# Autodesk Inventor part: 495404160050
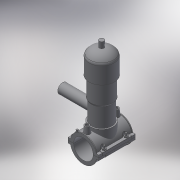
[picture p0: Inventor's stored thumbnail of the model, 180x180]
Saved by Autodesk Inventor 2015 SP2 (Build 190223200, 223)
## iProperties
Created: 2017-07
Part Number: 495404160050
Material: Generic
Description: PLASSON TAPPING VALVE 160-50
Document SubType Name: Modeling
Designer: KIM
Density: 1 g/cm^3
Appearance: Default
Author: KIM
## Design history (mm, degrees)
derived "495404-4954S4.ipt"
feature "Solid1::495404-4954S4.ipt"
feature "Solid2::495404-4954S4.ipt"
tag "TaggingFeature1"
body "Solid1"
body "Solid2"
other parameters: "d2" = 202, "d4" = 118, "d5" = 0, "d6" = 0.1, "d8" = 0, "d19" = 6, "d20" = 6, "d21" = 70.8, "d23" = 0, "d24" = 35.4, "d26" = 0, "d27" = 3, "d28" = 3, "d29" = 3, "d30" = 53.33333, "d31" = 6, "d32" = 0, "d33" = 0, "d34" = 0.6, "d40" = 99.84, "d47" = 147, "d70" = 15, "d72" = 0, "d73" = 6, "d75" = 5, "d76" = 0, "d77" = 8, "d79" = 15, "d80" = 47.2, "d82" = 5 deg, "d84" = 4, "d85" = 14, "d86" = 0, "d87" = 3, "d88" = 0, "d89" = 1, "d90" = 1, "d91" = 94.4, "d92" = 0, "d93" = 0.5, "d94" = 84.21053, "d96" = 197.76, "d97" = 2.36, "d98" = 0, "d120" = 140 deg, "d121" = 24.228, "d122" = 20 deg, "d123" = 384, "d124" = 115.2, "d126" = 0, "d143" = 164.8, "d145" = 24.61538, "d149" = 2.4, "d150" = 27.07692, "d153" = 118, "d154" = 0, "d156" = 96, "d157" = 160 deg, "d159" = 6.4, "d161" = 2.4, "d162" = 70.8, "d163" = 0, "d167" = 16, "d168" = 93.65854, "d170" = 3, "d172" = 0, "d173" = 1, "d176" = 20 deg, "d177" = 11.2, "d178" = 32, "d180" = 0, "d183" = 12.8, "d184" = 8.96, "d185" = 38.35, "d186" = 38.35, "d187" = 96, "d188" = 9.6, "d189" = 11.2, "d190" = 0, "d191" = 144, "d193" = 6.8, "d194" = 2.95, "d195" = 90 deg, "d197" = 0, "d199" = 0, "d205" = 14.64, "d206" = 81.33333, "d207" = 244, "d208" = 224.48, "d209" = 207.4, "d210" = 200.08, "d211" = 146.4, "d212" = 85.4, "d213" = 65.88, "d214" = 73.2, "d216" = 19.52, "d217" = 70.76, "d218" = 80.52, "d222" = 0, "d223" = 192, "d224" = 152, "d225" = 51, "d229" = 152, "d230" = 0, "B_" = 202, "H_" = 152, "L_" = 118, "d_t" = 6, "H_1" = 51, "H_2" = 244, "d148" = 2.4, "d160" = 2.4, "d169" = 3, "d192" = 6.8
